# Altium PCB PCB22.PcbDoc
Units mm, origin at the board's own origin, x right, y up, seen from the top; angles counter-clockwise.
Board outline 66.13 x 50.42 mm, 2 copper layers (Top Layer, Bottom Layer), stack 1 mm thick; 21 components, 17 nets, 100 pads, 0 vias.
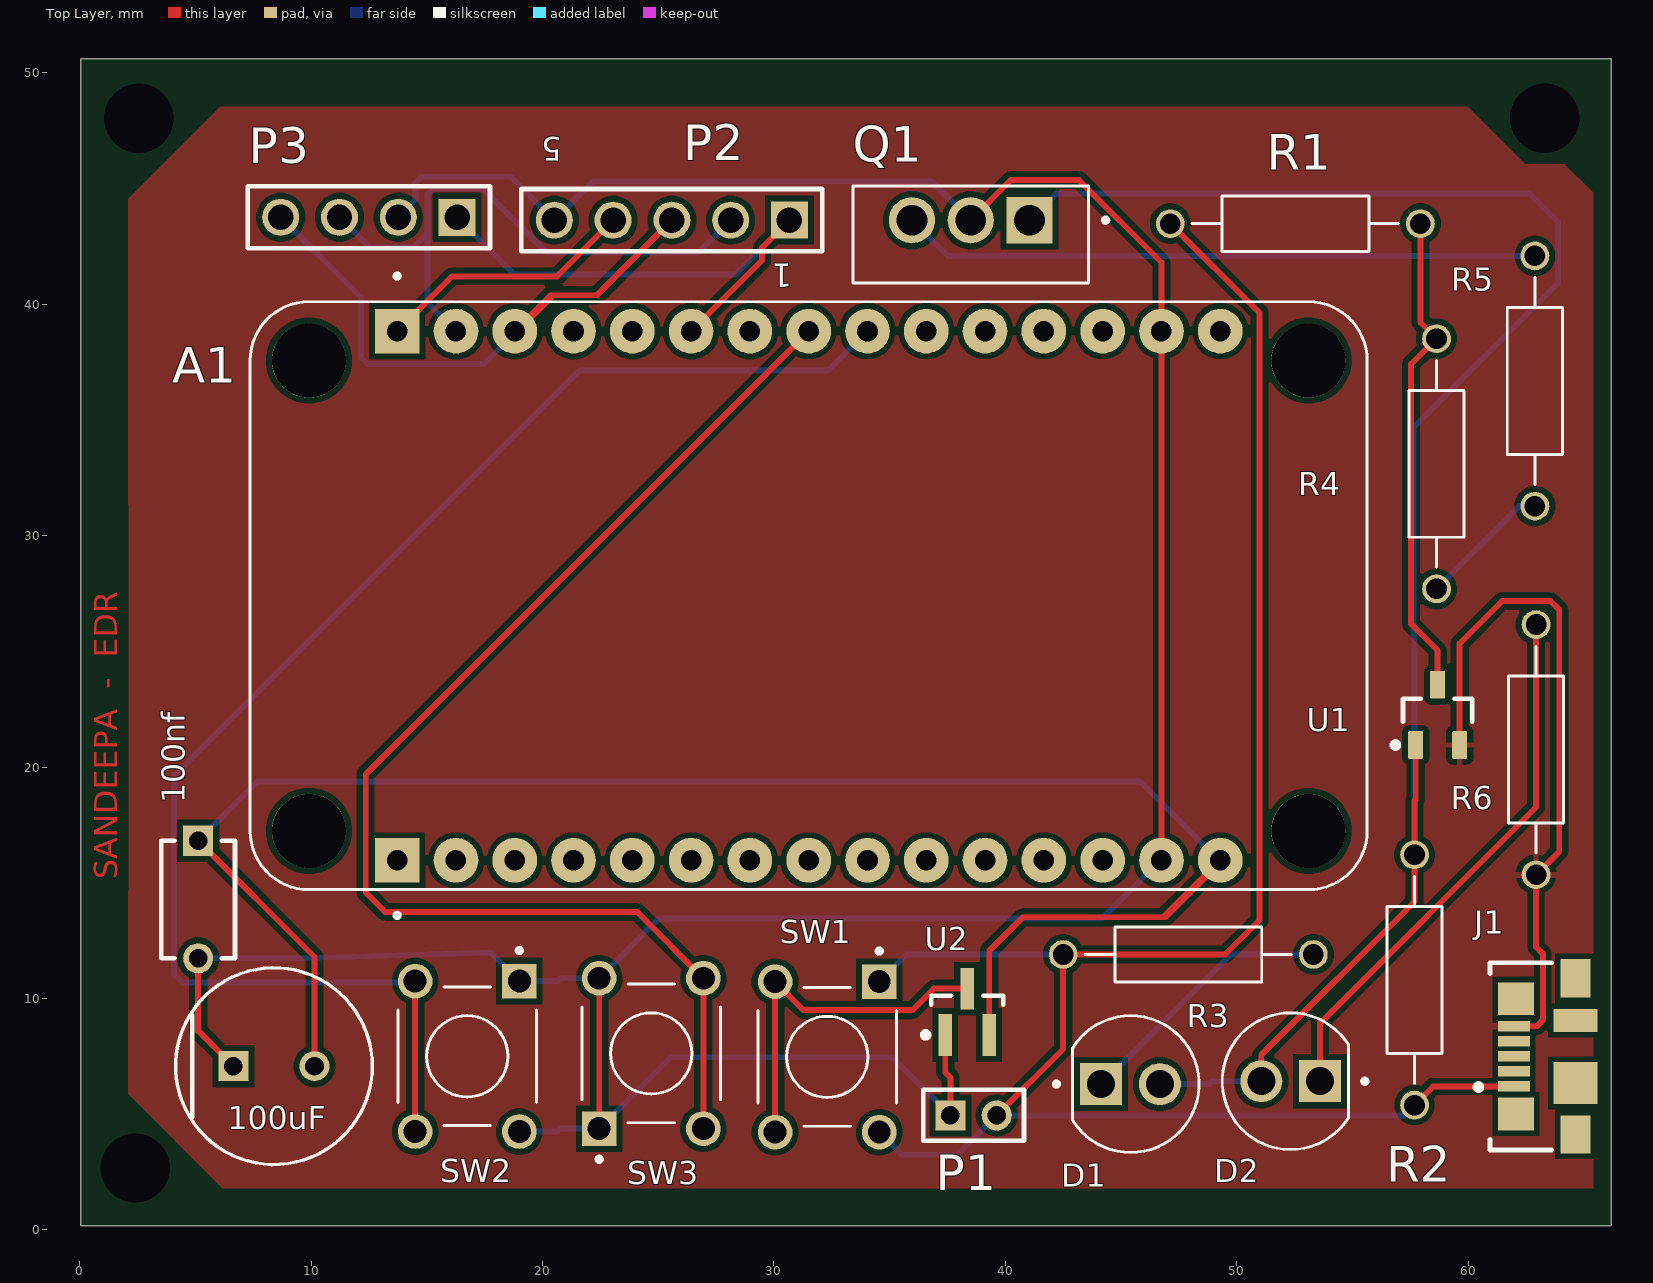
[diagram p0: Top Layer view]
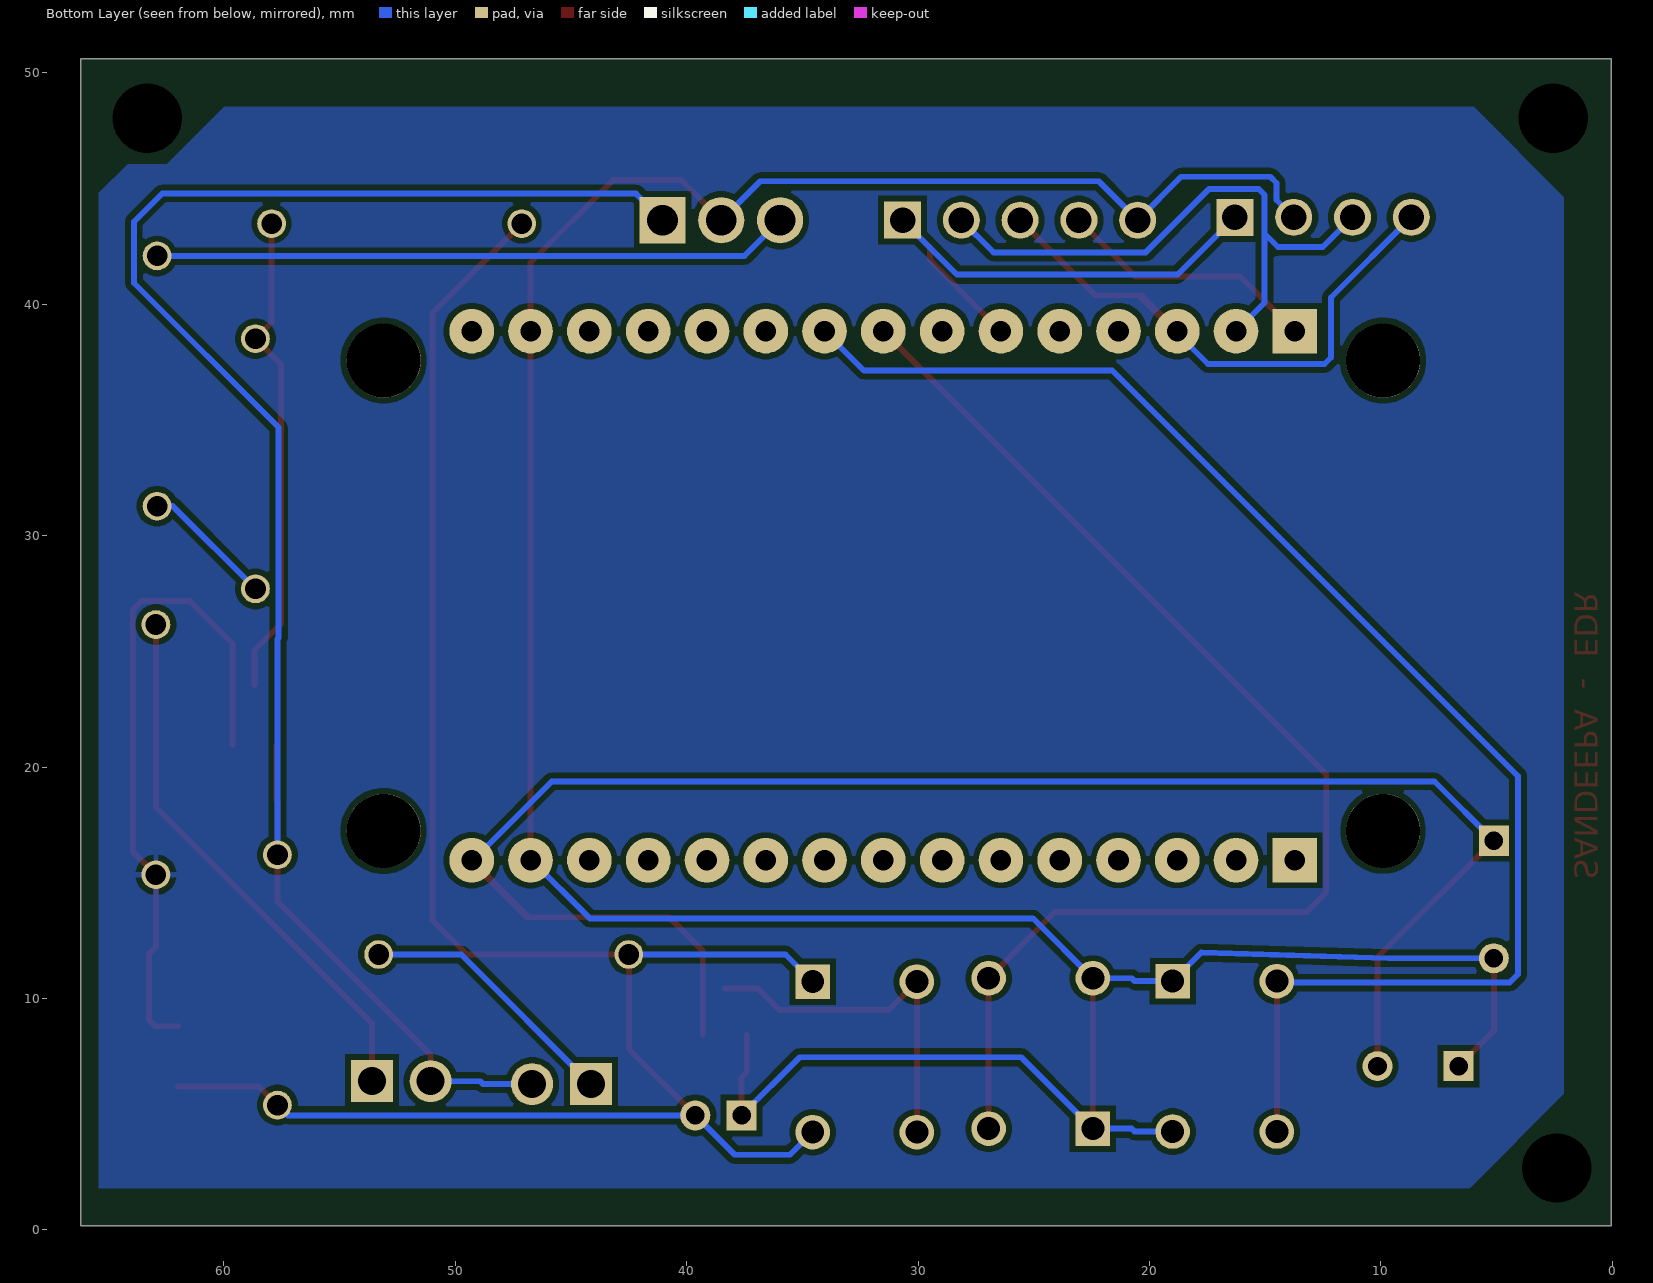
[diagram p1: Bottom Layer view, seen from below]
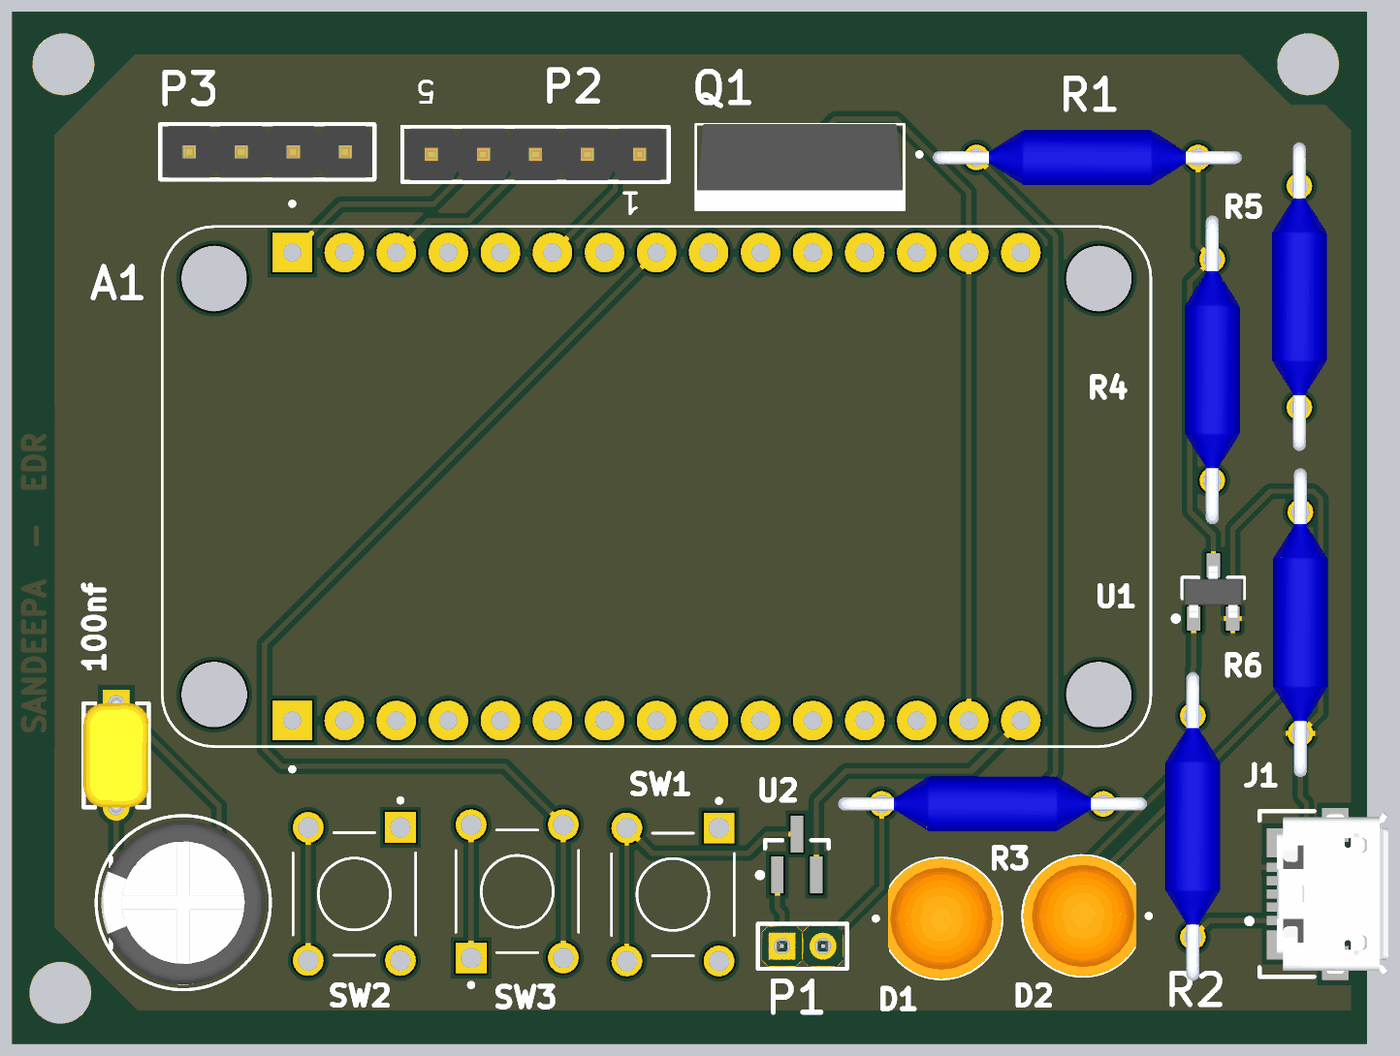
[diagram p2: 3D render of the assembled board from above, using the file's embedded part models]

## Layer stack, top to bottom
Top Solder: solder mask 0.5, SM-001, Dk 4
Top Layer: signal copper 0.1
Dielectric 1: dielectric 0.8, FR-4, Dk 4.8
Bottom Layer: signal copper 0.1
Bottom Solder: solder mask 0.5, SM-001, Dk 4

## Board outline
0.05,0.175 66.175,0.175 66.175,50.6 0.05,50.6

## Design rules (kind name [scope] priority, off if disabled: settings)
Clearance [All] p1: gap=0.2 ignorepadtopadclearanceinfootprint=FALSE
HoleSize [All] p1: absolutevalues=TRUE maxlimit=3.5 minlimit=0.025 maxpercent=80.000 minpercent=20.000
MinimumSolderMaskSliver [All] p1: minsoldermaskwidth=0.14
PolygonConnect [All] p1: connectstyle=Relief reliefconductorwidth=0.254 reliefentries=4 polygonreliefangle="90 Angle" airgapwidth=0.254
RoutingVias [All] p1: holewidth=0.4 width=0.5 viastyle="Through Hole" minholewidth=0.4 minwidth=0.5 maxholewidth=0.4 maxwidth=0.5
SilkToSilkClearance [All] p1: silktosilkclearance=0.2
SilkToSolderMaskClearance [IsPad] p1: minsilkscreentomaskgap=0.2 clearancetoexposedcopper=TRUE
SolderMaskExpansion [All] p1: expansion=0.102 istentingtop=FALSE
Width Width_1 [All] p1: maxlimit=0.254 minlimit=0.254 preferedwidth=0.254
Width [All] p2: maxlimit=0.3 minlimit=0.2 preferedwidth=0.2
26 further rules are at their usual default settings.

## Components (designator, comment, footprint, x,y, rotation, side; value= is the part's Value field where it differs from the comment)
100nf "C322C104K5R5TA" FP-C322C104K5R5TA-MFG 5.125,14.275 r270 top
100uF "EEUTA1E101" FP-RAD-TH-D_8_0_5-L_11_5-MFG 8.4,7.075 r0 top
A1 "113990105" SEEED_113990105 31.5,27.4 r90 top
D1 "Green" LEDRD254W57D500H1070 45.405,6.3 r0 top
D2 "Red" LEDRD254W57D500H1070 52.325,6.425 r180 top
J1 "473460001" FP-473460001-MFG 64.285,7.5 r90 top
P1 "M22-2510205" FP-M22-2510205-MFG 38.625,4.95 r0 top
P2 "61300511121" 61300511121 25.59,43.625 r180 top
P3 "61300411121" 61300411121 12.5,43.75 r180 top
Q1 "IRFZ44NPBF" TO254P1016X419X2286-3 38.5,43.625 r180 top
R1 "4.7k" RESAD1081W64L635D269 52.525,43.475 r180 top
R2 "1k" RESAD1081W64L635D269 57.675,10.8 r270 top
R3 "5.6k" RESAD1081W64L635D269 47.9,11.9 r180 top
R4 "4.7k" RESAD1081W64L635D269 58.625,33.1 r90 top
R5 "220" RESAD1081W64L635D269 62.875,36.675 r270 top
R6 "15k" RESAD1081W64L635D269 62.925,20.75 r270 top
SW1 "1825910-2" TE_1825910-2 34.55,10.725 r270 top
SW2 "1825910-2" TE_1825910-2 19,10.75 r270 top
SW3 "1825910-2" TE_1825910-2 22.45,4.375 r90 top
U1 "TL431AQDBZR" DBZ0003A_M 58.675,22.25 r90 top
U2 "MCP1700T-1802E/TT" SOT-23-TT3_M 38.35,9.425 r90 top

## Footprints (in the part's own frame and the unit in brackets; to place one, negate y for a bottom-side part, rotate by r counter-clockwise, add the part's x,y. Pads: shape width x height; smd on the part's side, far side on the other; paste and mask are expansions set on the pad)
61300411121 [mm] "Pin Header, pitch 2.54 mm, THT, Vertical, single row, 4p"
  rect 1.6x1.6 hole 1.1: 1(-3.81,0)
  round 1.6 hole 1.1: 2(-1.27,0) 3(1.27,0) 4(3.81,0)
  silkscreen extent -5.23,-1.35 5.23,1.34, body extent -5.08,-1.27 5.08,1.27, height 8.57
61300511121 [mm] "Pin Header, pitch 2.54 mm, THT, Vertical, single row, 5p"
  rect 1.6x1.6 hole 1.1: 1(-5.08,0)
  round 1.6 hole 1.1: 2(-2.54,0) 3(0,0) 4(2.54,0) 5(5.08,0)
  silkscreen extent -6.5,-1.35 6.5,1.34, body extent -6.35,-1.27 6.35,1.27, height 8.57
DBZ0003A_M [mm] "SOT23, 3-Leads, Body 3.04x1.4mm, Pitch 0.95mm, IPC Low Density"
  rrect15% 1.2x0.65 smd: 1(-1.3,0.95) 2(-1.3,-0.95) 3(1.3,0)
  silkscreen extent -1.42,-1.5 0.7,1.95, body extent -1.26,-1.46 1.26,1.46, height 0.96
FP-473460001-MFG [mm]
  rect 0.45x1.38 smd paste+0 mask+0: 1(-1.3,2.31) 2(-0.65,2.31) 3(0,2.31) 4(0.65,2.31) 5(1.3,2.31)
  rect 1.425x1.55 smd paste+0 mask+0: 6(-2.487,2.225) 7(2.488,2.225)
  rect 1.65x1.3 smd paste+0 mask+0: 8(-3.375,-0.35) 11(3.375,-0.35)
  rect 1.8x1.9 smd paste+0 mask+0: 9(-1.15,-0.35)
  rect 1x1.9 smd paste+0 mask+0: 10(1.55,-0.35)
  silkscreen extent -4.04,0.68 4.05,3.97, body extent -4.3,-2.48 4.3,3.45, height 0.25
FP-C322C104K5R5TA-MFG [mm]
  rect 1.3x1.3 hole 0.8 paste-1000 mask+0: 1(-2.54,0)
  round 1.3 hole 0.8 paste-1000 mask+0: 2(2.54,0)
  silkscreen extent -2.54,-1.59 2.54,1.59, body extent -3.29,-1.69 3.29,1.69, height 0.25
FP-M22-2510205-MFG [mm]
  rect 1.3x1.3 hole 0.8 paste-1000 mask+0: 1(-1,0)
  round 1.3 hole 0.8 paste-1000 mask+0: 2(1,0)
  silkscreen extent -2.17,-1.1 2.17,1.1, body extent -2.27,-1.2 2.27,1.2, height 0.25
FP-RAD-TH-D_8_0_5-L_11_5-MFG [mm]
  rect 1.3x1.3 hole 0.8 paste-1000 mask+0: 1(-1.75,0)
  round 1.3 hole 0.8 paste-1000 mask+0: 2(1.75,0)
  silkscreen extent -4.25,-4.25 4.25,4.25, body extent -4.35,-4.35 4.35,4.35, height 0.25
LEDRD254W57D500H1070 [mm]
  round 1.815 hole 1.21: A(1.27,0)
  rect 1.815x1.815 / inner round 1.815 / far side rect 1.815x1.815 hole 1.21: C(-1.27,0)
  silkscreen extent -3.3,-2.96 2.96,2.96, body extent -2.6,-2.95 2.95,2.95, height 9.1
RESAD1081W64L635D269 [mm]
  round 1.24 hole 0.89: 1(-5.405,0) 2(5.405,0)
  silkscreen extent -4.46,-1.2 4.46,1.19, body extent -7.54,-1.35 7.54,1.35, height 2.69
SEEED_113990105 [mil]
  rect 75.98x75.98 / inner round 75.98 / far side rect 75.98x75.98 hole 35: J1_1(-450,700) J2_1(450,700)
  round 75.98 hole 35: J1_2(-450,600) J1_3(-450,500) J1_4(-450,400) J1_5(-450,300) J1_6(-450,200) J1_7(-450,100) J1_8(-450,0) J1_9(-450,-100) J1_10(-450,-200) J1_11(-450,-300) J1_12(-450,-400) J1_13(-450,-500) J1_14(-450,-600) J1_15(-450,-700) J2_2(450,600) J2_3(450,500) J2_4(450,400) J2_5(450,300) J2_6(450,200) J2_7(450,100) J2_8(450,0) J2_9(450,-100) J2_10(450,-200) J2_11(450,-300) J2_12(450,-400) J2_13(450,-500) J2_14(450,-600) J2_15(450,-700)
  round 125.98 hole 125.98 unplated: ""(-400,850) ""(-400,-850) ""(400,850) ""(400,-850)
  silkscreen extent -548,-950 548,950
SOT-23-TT3_M [mm] "SOT23, 3-Leads, Body 2.9x1.3mm, Pitch 0.95mm, Lead Span 2.4mm, IPC Low Density"
  rect 1.8x0.6 smd: 1(-1,0.95) 2(-1,-0.95) 3(1,0)
  silkscreen extent -1.12,-1.55 0.7,1.92, body extent -0.7,-1.52 0.7,1.53, height 1.12
TE_1825910-2 [mm]
  rect 1.498x1.498 / inner round 1.498 / far side rect 1.498x1.498 hole 0.99: 1(0,0)
  round 1.498 hole 0.99: 2(6.5,0) 3(0,-4.5) 4(6.5,-4.5)
  silkscreen extent -1.42,-5.24 6.25,0.74
TO254P1016X419X2286-3 [mm]
  rect 1.995x1.995 / inner round 1.995 / far side rect 1.995x1.995 hole 1.33: 1(-2.54,0)
  round 1.995 hole 1.33: 2(0,0) 3(2.54,0)
  silkscreen extent -5.93,-1.48 5.08,2.72, body extent -5.08,-1.47 5.08,2.72, height 22.86

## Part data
100nf: library part CMP-03020-034661-1, "CAP CER 0.1UF 50V X7R RADIAL", Capacitance=100nF, Case/Package=Radial, Dielectric=X7R, Dielectric Material=Ceramic, Max Operating Temperature=125°C, Min Operating Temperature=-55°C, Package Quantity=500, Tolerance=10%, Voltage=50V
100uF: library part CMP-05427-002094-1, "Aluminum Electrolytic Capacitors (Radial Lead Type) AEC-Q200 Qualified 100uF ±20% 25V", Capacitance=100uF, Case/Package=Radial, Dielectric Material=Aluminium, ESR (Equivalent Series Resistance)=130mR, Leakage Current=25uA, Max Operating Temperature=125°C, Min Operating Temperature=-40°C, Package Quantity=200, Ripple Current=500mA, Tolerance=20%, Voltage=25V
A1: "- ESP8266 Transceiver; 802.11 b/g (Wi-Fi, WiFi, WLAN) 2.4GHz Evaluation Board", Package=None
D1 D2: library part L08R5000Q1, "LED, 5MM, ORANGE; LED / Lamp Size: 5mm / T-1 3/4; LED Colour: Orange; Typ Luminous Intensity: 4.3mcd; Viewing Angle: ...", Package=None
J1: library part 10118193-0001LF, "Micro USB 2.0, Input Output Connectors, B TYPE RECEPTACLE", Package=None
P1: library part CMP-15831-000005-1, "CONN HEADER VERT 2POS 2MM", Current Rating=2A, Manufacturer=Harwin, Package=0, Temperature="-40°C to +105°C", Temperature Range High=+105°C, Temperature Range Low=-40°C
P2: library part CMP-1502-01068-1, "THT Vertical Pin Header WR-PHD, Pitch 2.54 mm, Single Row, 5 pins", Contact Resistance=20mOhm, Manufacturer="Wurth Elektronik", Operating Temperature=-40to105degC, Rated Current=3A, Withstanding Voltage=500VAC, Working Voltage=250VAC
P3: library part CMP-1502-01064-1, "THT Vertical Pin Header WR-PHD, Pitch 2.54 mm, Single Row, 4 pins", Contact Resistance=20mOhm, Manufacturer="Wurth Elektronik", Operating Temperature=-40to105degC, Rated Current=3A, Withstanding Voltage=500VAC, Working Voltage=250VAC
Q1: "N-Channel 55 V 49A (Tc) 94W (Tc) Through Hole TO-220AB", Package="TO-220-3 Infineon"
R1 R2 R3 R4 R5 R6: library part RNC55H4701BSB14, "4.7 kOhms Â±0.1% 0.125W, 1/8W Through Hole Resistor Axial Military, Moisture Resistant, Weldable Metal Film", Package="erc55 Vishay"
SW1 SW2 SW3: "50 mA SPST Round Actuator 160 Gram Force Tactile Pushbutton Switch", Package=None
U1: library part CMP-0366-01210-2, "Adjustable Precision Shunt Regulator, 34 ppm / degC, 100 mA, -40 to 125 degC, 3-pin SOT-23 (DBZ), Green (RoHS & no Sb/Br)", Manufacturer="Texas Instruments", Rating=Catalog, Temp Coeff(Max)(ppm/ degree C)=92, Temp Coeff(Typ)(ppm/ degree C)=34
U2: library part CMP-0136-00773-1, "Low Quiescent Current LDO, 3-Pin SOT-23, Extended Temperature, Tape and Reel"

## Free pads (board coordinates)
  round 1.524 hole 3: 7(2.55,48.025) 8(63.3,48.025) 9(2.4,2.675)

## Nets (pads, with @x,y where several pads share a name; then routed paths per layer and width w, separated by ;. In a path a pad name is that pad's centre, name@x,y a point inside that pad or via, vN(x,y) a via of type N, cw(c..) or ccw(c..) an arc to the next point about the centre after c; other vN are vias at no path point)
3.3v: A1.J2_6 P2.1 P3.1 | length 22.9
  Top Layer w0.254: A1.J2_6 29.482,41.892 29.482,42.437 P2.1
  Bottom Layer w0.254: P3.1 18.79,41.27 28.315,41.27 P2.1
B+: J1.1 P1.2 R1.2 R2.2 R3.2 SW1.1 SW1.2 | length 86.4
  Top Layer w0.254: P1.2 42.495,7.82 R3.2 49.49,11.9 50.975,13.385 50.975,39.62 R1.2 ; R2.2 58.48,6.2 J1.1
  Bottom Layer w0.254: SW1.2 35.529,3.246 37.921,3.246 P1.2 57.23,4.95 R2.2 ; SW1.1 35.725,11.9 R3.2
B-: 100nf.2 100uF.1 A1.J1_14 A1.J2_14 P1.1 P2.5 P3.2 Q1.2 SW2.1 SW2.2 SW3.1 SW3.2 U2.1 | length 145
  Top Layer w0.254: 100nf.2 5.125,8.6 100uF.1 ; SW3.1 SW3.2 ; U2.1 37.4,6.799 37.625,6.574 P1.1 ; Q1.2 40.234,45.359 43.173,45.359 46.74,41.792 A1.J2_14 46.74,16.02 A1.J1_14
  Bottom Layer w0.254: 100nf.2 9.676,11.735 17.766,11.984 SW2.1 20.643,10.75 20.768,10.875 SW3.2 25.034,13.459 44.179,13.459 A1.J1_14@46.74,16.02 ; P3.2 14.513,44.493 14.513,45.23 14.782,45.499 18.636,45.499 P2.5 22.191,45.306 36.819,45.306 Q1.2 ; SW2.2 20.643,4.25 20.768,4.375 SW3.1 25.538,7.463 35.112,7.463 P1.1
GND: J1.5 R6.2 U1.2 | length 29.2
  Top Layer w0.254: U1.2 59.625,25.337 61.461,27.173 63.544,27.173 63.925,26.792 63.925,16.345 R6.2 62.925,12.23 63.22,11.935 63.22,9.065 62.955,8.8 J1.5
NetA1_J2_1: A1.J2_1 P2.4 | length 11.3
  Top Layer w0.254: A1.J2_1 16.084,41.194 20.619,41.194 P2.4
NetA1_J2_2: A1.J2_2 P2.2 P3.3 | length 25.9
  Bottom Layer w0.254: P3.3 12.516,42.464 14.446,42.464 15.03,43.048 ; A1.J2_2 15.03,40.06 15.03,43.048 ; P2.2 26.74,42.235 20.163,42.235 17.42,44.978 15.29,44.978 15.03,44.718 15.03,43.048
NetA1_J2_3: A1.J2_3 P2.3 P3.4 | length 25.9
  Top Layer w0.254: A1.J2_3 20.351,40.381 20.461,40.381 ; A1.J2_3@18.82,38.76 18.84,38.76 20.461,40.381 ; P2.3 22.346,40.381 20.461,40.381
  Bottom Layer w0.254: P3.4 12.16,40.28 12.16,37.689 12.439,37.409 17.469,37.409 A1.J2_3@18.82,38.76
NetA1_J2_8: A1.J2_8 SW3.3 SW3.4 | length 54.8
  Top Layer w0.254: SW3.3 SW3.4 24.089,13.736 13.201,13.736 12.363,14.575 12.363,19.693 A1.J2_8
NetA1_J2_9: A1.J2_9 SW2.3 SW2.4 | length 63.6
  Top Layer w0.254: SW2.4 SW2.3
  Bottom Layer w0.254: SW2.3 14.438,10.688 4.438,10.688 4.082,11.044 4.082,19.604 21.608,37.13 32.34,37.13 A1.J2_9
NetD1_A: D1.A D2.A Q1.1 R2.1 U1.1 | length 75.5
  Top Layer w0.254: D2.A 51.055,7.564 57.675,14.184 R2.1 57.675,18.537 57.725,18.587 U1.1
  Bottom Layer w0.254: Q1.1 42.19,44.775 62.655,44.775 63.874,43.556 63.874,40.914 57.626,34.666 57.626,25.573 57.675,25.523 R2.1 ; D1.A 48.786,6.3 48.911,6.425 D2.A
NetD1_C: D1.C R3.1 | length 11.5
  Bottom Layer w0.254: D1.C 49.735,11.9 R3.1
NetD2_C: D2.C R6.1 | length 23.6
  Top Layer w0.254: D2.C 53.595,8.936 62.925,18.266 R6.1
NetQ1_3: Q1.3 R5.1 | length 27.6
  Bottom Layer w0.254: Q1.3 37.505,42.08 R5.1
NetR1_1: R1.1 R4.2 U1.3 | length 21.1
  Top Layer w0.254: R1.1 57.93,39.2 R4.2 57.524,37.404 57.524,26.182 58.675,25.031 U1.3
NetR4_1: R4.1 R5.2 | length 5.7
  Bottom Layer w0.254: R4.1 62.2,31.27 R5.2
NetSW1_3: SW1.3 SW1.4 U2.3 | length 15.7
  Top Layer w0.254: SW1.4 SW1.3 31.28,9.495 35.985,9.495 36.915,10.425 U2.3
Vin: 100nf.1 100uF.2 A1.J1_15 U2.2 | length 77.2
  Top Layer w0.254: 100nf.1 10.15,11.79 100uF.2 ; U2.2 39.3,12.06 40.748,13.508 46.818,13.508 ; A1.J1_15 46.818,13.508 ; A1.J1_15@49.3,15.9 46.908,13.508 46.818,13.508
  Bottom Layer w0.254: 100nf.1 7.685,19.375 45.825,19.375 A1.J1_15@49.3,15.9
pads on no net: A1. A1.J1_1 A1.J1_2 A1.J1_3 A1.J1_4 A1.J1_5 A1.J1_6 A1.J1_7 A1.J1_8 A1.J1_9 A1.J1_10 A1.J1_11 A1.J1_12 A1.J1_13 A1.J2_4 A1.J2_5 A1.J2_7 A1.J2_10 A1.J2_11 A1.J2_12 A1.J2_13 A1.J2_15 J1.2 J1.3 J1.4 J1.6 J1.7 J1.8 J1.9 J1.10 J1.11

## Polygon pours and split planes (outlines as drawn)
GND on Top Layer "GND_L01_P001" (solid, pour order 1): 6.075,48.525 2.1,44.55 2.1,5.875 6.175,1.8 65.4,1.8 65.4,44.8 64.15,46.05 62.45,46.05 59.975,48.525 6,48.525
GND on Bottom Layer "GND_L02_P002" (solid, pour order 2): 6,48.525 59.975,48.525 62.45,46.05 64.15,46.05 65.4,44.8 65.4,1.8 6.175,1.8 2.1,5.875 2.1,44.625

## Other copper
Top Layer:
  text "SANDEEPA  -  EDR" at 1.621,15.154 h1 r90

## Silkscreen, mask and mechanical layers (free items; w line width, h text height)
Mechanical 1:
  lines w0.2: 66.175,50.55 66.175,0.175 66.15,0.15 0.125,0.15 0.05,0.225 0.05,50.55 66.175,50.55 ; 66.175,50.55 66.175,50.55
